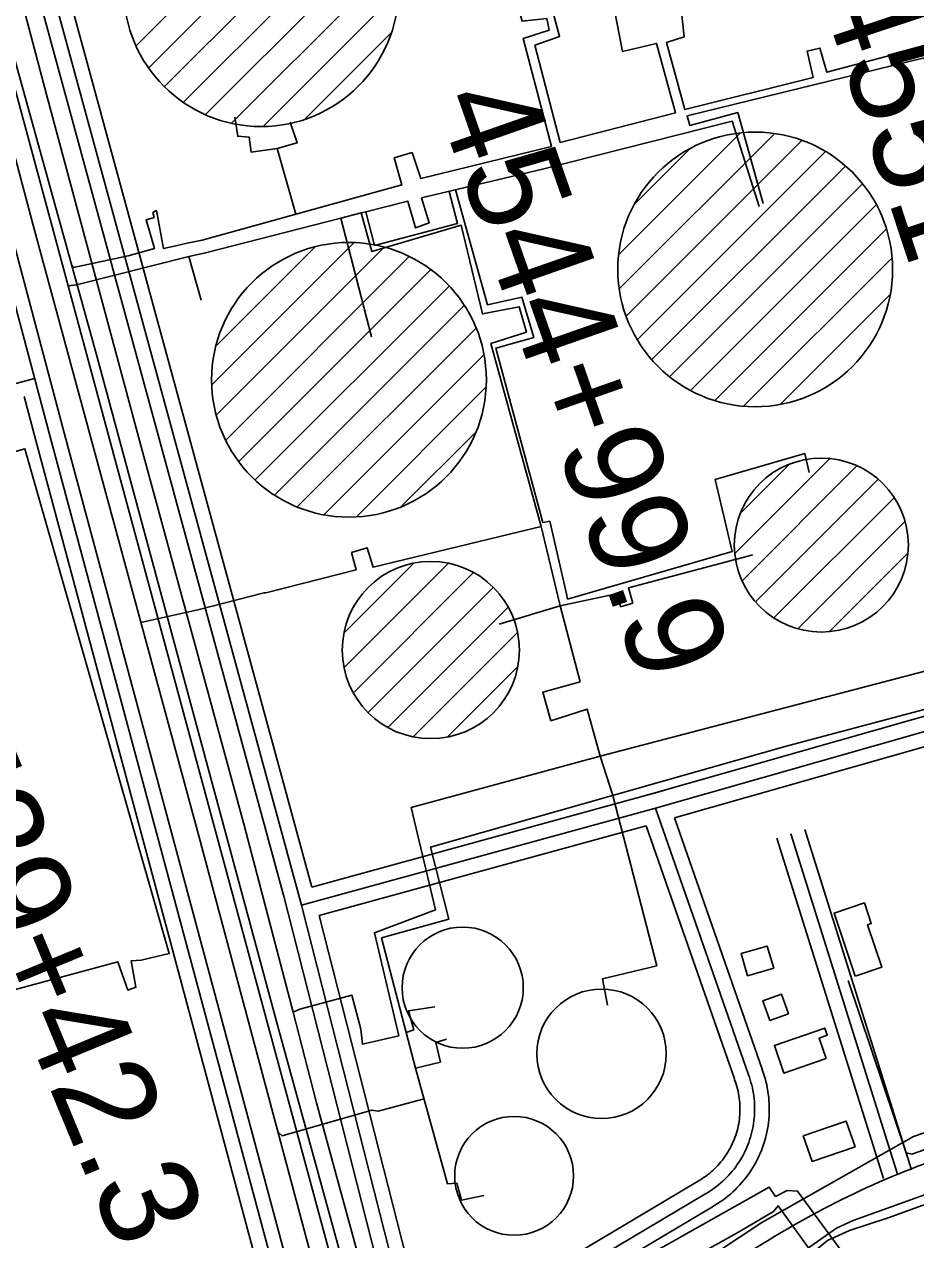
# Model space of a CAD drawing. Extents: x 3508733 to 3546731, y 546897 to 572481.
# Drawn here: x 3514220 to 3515132, y 565615 to 566859 of the extents above; entities that cross this region are included whole.
import ezdxf

# ---------------------------------------------------------------- set-up
doc = ezdxf.new("R2010")
doc.units = 0
for name, color, linetype in [('V-BLDG-OTLN', 7, 'Continuous'), ('V-DOMW-TANK', 7, 'Continuous'), ('V-LEVE-TOET', 7, 'Continuous'), ('V-ROAD-CNTR', 7, 'Continuous'), ('V-SITE-OTLN', 7, 'Continuous'), ('V-SURV-IDEN', 7, 'Continuous'), ('V-TOPO-SHOR', 7, 'Continuous'), ('V-UTIL-LINE', 7, 'Continuous')]:
    doc.layers.add(name, color=color, linetype=linetype)

msp = doc.modelspace()

# ---------------------------------------------------------------- linework, layer by layer
at = {"layer": 'V-BLDG-OTLN'}
for points in [[(3515069.8, 565884.8), (3515048.2, 565949.4), (3515079.3, 565959.8), (3515086.3, 565938.6), (3515082.6, 565937.4), (3515097.1, 565893.9)], [(3514986.5, 565892.9), (3514959.8, 565885.3), (3514953.4, 565907.9), (3514980, 565915.5)], [(3515001.7, 565846.3), (3514982.5, 565839.5), (3514975.4, 565859.6), (3514994.6, 565866.3)], [(3515040.1, 565800.5), (3514996.9, 565785.7), (3514987.3, 565813.9), (3515038.8, 565831.6), (3515041.3, 565824.3), (3515032.9, 565821.4)], [(3515069.7, 565710.3), (3515025.7, 565695.2), (3515016.7, 565721.3), (3515060.6, 565736.5)]]:
    msp.add_lwpolyline(points, close=True, dxfattribs=at)
at = {"layer": 'V-DOMW-TANK'}
for p, q in [((3514334.5, 566836.5), (3514520.3, 567022.3)), ((3514347.5, 566814.1), (3514542.8, 567009.5)), ((3514363.5, 566794.8), (3514562, 566993.3)), ((3514383, 566778.9), (3514578.1, 566974)), ((3514405.6, 566766.2), (3514590.7, 566951.3)), ((3514432.2, 566757.4), (3514599.4, 566924.7)), ((3514464.3, 566754.1), (3514602.7, 566892.6)), ((3514507, 566761.5), (3514595.6, 566850.1)), ((3514828.2, 566623.1), (3514952.3, 566747.2)), ((3514828.7, 566588.2), (3514987.2, 566746.7)), ((3514835.8, 566559.9), (3515015.4, 566739.6)), ((3514844.2, 566674.5), (3514900.9, 566731.1)), ((3514847, 566535.8), (3515039.5, 566728.3)), ((3514862, 566515.5), (3515059.9, 566713.4)), ((3514879.9, 566498), (3515077.3, 566695.4)), ((3514901.4, 566484.1), (3515091.3, 566674)), ((3514926.2, 566473.6), (3515101.8, 566649.2)), ((3514411.9, 566489.7), (3514557.6, 566635.3)), ((3514416.2, 566529.3), (3514517.8, 566630.9)), ((3514416.6, 566459), (3514588.2, 566630.6)), ((3514426.2, 566433.2), (3514613.9, 566620.9)), ((3514955.7, 566467.8), (3515107.4, 566619.4)), ((3514439.5, 566411.2), (3514636, 566607.7)), ((3514456.3, 566392.6), (3514654.5, 566590.8)), ((3514993, 566469.7), (3515105.6, 566582.3)), ((3514476, 566377), (3514670.2, 566571.2)), ((3514499.4, 566365), (3514682.2, 566547.7)), ((3514526.6, 566356.9), (3514690.2, 566520.4)), ((3514559.8, 566354.7), (3514692.3, 566487.2)), ((3514605.4, 566364.9), (3514681.9, 566441.4)), ((3514946.7, 566317.3), (3515043.6, 566414.2)), ((3514952.4, 566358.3), (3515002.4, 566408.4)), ((3514954.2, 566289.4), (3515071.6, 566406.8)), ((3514967.9, 566267.8), (3515093.2, 566393.1)), ((3514986.8, 566251.3), (3515109.6, 566374.2)), ((3515011.1, 566240.3), (3515120.6, 566349.8)), ((3515043.5, 566237.3), (3515123.8, 566317.7)), ((3514547.2, 566200.6), (3514653.6, 566307.1)), ((3514547.3, 566236.1), (3514618.3, 566307.1)), ((3514556.7, 566174.8), (3514679.6, 566297.7)), ((3514571.8, 566154.5), (3514699.7, 566282.4)), ((3514591.9, 566139.3), (3514714.9, 566262.3)), ((3514617.7, 566129.7), (3514724.4, 566236.5)), ((3514653.1, 566129.8), (3514724.5, 566201.2))]:
    msp.add_line(p, q, dxfattribs=at)
for centre, radius in [((3514462.4, 566894.5), 140.5), ((3514967.6, 566607.8), 140.5), ((3514552.2, 566494.9), 140.5), ((3515035.2, 566325.8), 89), ((3514635.9, 566218.4), 90.6), ((3514668.5, 565873), 62), ((3514810.5, 565805.4), 66.2), ((3514721.1, 565680.5), 60.8)]:
    msp.add_circle(centre, radius, dxfattribs=at)
at = {"layer": 'V-LEVE-TOET'}
msp.add_lwpolyline([(3514850.8, 565476.6), (3514903.4, 565510.7), (3515017.6, 565594.7), (3515041.7, 565614.3), (3515064, 565624.5), (3515103.4, 565637.7), (3515402.4, 565746.1), (3515714.9, 565848.8), (3515765.6, 565860.9), (3516060.6, 565934), (3516227.3, 565973.3), (3516431, 566026.4), (3516563, 566047.8)], dxfattribs=at)
at = {"layer": 'V-ROAD-CNTR'}
for points in [[(3514503.5, 565957.3), (3514208.7, 567040.6), (3514013, 567794.7)], [(3514547.8, 565330.7), (3514512.1, 565447.2), (3514246.5, 566436.7), (3513987, 567414.4), (3513945.8, 567576.4)], [(3514485.1, 565967.8), (3514197.9, 567023.2)], [(3514514.1, 565975.8), (3514226.9, 567030.9)], [(3514562.1, 565335), (3514526.5, 565451.4), (3514261, 566440.6), (3514112.4, 567000.6)], [(3513312, 566249), (3514230.7, 566496.3)], [(3514494.6, 565454.6), (3514232, 566432.8), (3514220, 566477.9)], [(3515710.1, 566312.9), (3514859.2, 566070.6), (3514514.1, 565975.8)], [(3515714.2, 566298.4), (3514863.3, 566056.1), (3514503.5, 565957.3), (3514615.1, 565518.5)], [(3515326.2, 566172.3), (3514885.1, 566046.8)], [(3514875.3, 566075), (3514859.5, 566070.6)], [(3514960.4, 565784.8), (3514865.8, 566056.8), (3514862.5, 566055.9)], [(3514856.2, 566038.6), (3514521.7, 565946.7), (3514629.7, 565522.2)], [(3514946.3, 565779.8), (3514856.2, 566038.6)], [(3514974.6, 565789.7), (3514885.1, 566046.8)], [(3515098.9, 565677.7), (3514989.6, 566025.9)], [(3515113.2, 565682.2), (3515003.9, 566030.4)], [(3515127.5, 565686.7), (3515018.2, 566034.9)], [(3514485.4, 565967.9), (3514485.4, 565967.9), (3514600.6, 565514.9)], [(3514923.8, 565648.8), (3514926.4, 565650.4), (3514929.2, 565652.1), (3514931.9, 565653.9), (3514934.6, 565655.8), (3514937.2, 565657.7), (3514939.7, 565659.7), (3514942.2, 565661.8), (3514944.6, 565664), (3514947, 565666.2), (3514949.3, 565668.5), (3514951.5, 565670.9), (3514953.7, 565673.3), (3514955.8, 565675.8), (3514957.9, 565678.4), (3514959.8, 565681), (3514961.7, 565683.6), (3514963.5, 565686.3), (3514965.2, 565689.1), (3514966.9, 565691.9), (3514968.5, 565694.7), (3514970, 565697.6), (3514971.4, 565700.6), (3514972.7, 565703.5), (3514973.9, 565706.5), (3514975.1, 565709.6), (3514976.2, 565712.7), (3514977.1, 565715.8), (3514978, 565718.9), (3514978.8, 565722), (3514979.6, 565725.2), (3514980.2, 565728.4), (3514980.7, 565731.6), (3514981.2, 565734.8), (3514981.5, 565738.1), (3514981.8, 565741.3), (3514982, 565744.6), (3514982, 565747.8), (3514982, 565751.1), (3514981.9, 565754.3), (3514981.7, 565757.6), (3514981.4, 565760.8), (3514981, 565764.1), (3514980.6, 565767.3), (3514980, 565770.5), (3514979.4, 565773.7), (3514978.6, 565776.9), (3514977.8, 565780), (3514976.9, 565783.1), (3514975.9, 565786.2), (3514974.8, 565789.2), (3514974.5, 565790.1)], [(3514908.6, 565674.7), (3514910.9, 565676), (3514912.9, 565677.3), (3514914.9, 565678.7), (3514916.9, 565680), (3514918.8, 565681.5), (3514920.7, 565683), (3514922.6, 565684.5), (3514924.4, 565686.1), (3514926.1, 565687.8), (3514927.8, 565689.5), (3514929.5, 565691.2), (3514931.1, 565693), (3514932.6, 565694.9), (3514934.1, 565696.7), (3514935.6, 565698.7), (3514937, 565700.6), (3514938.3, 565702.6), (3514939.6, 565704.7), (3514940.8, 565706.7), (3514942, 565708.9), (3514943.1, 565711), (3514944.1, 565713.2), (3514945.1, 565715.4), (3514946, 565717.6), (3514946.9, 565719.8), (3514947.7, 565722.1), (3514948.4, 565724.4), (3514949.1, 565726.7), (3514949.7, 565729.1), (3514950.2, 565731.4), (3514950.7, 565733.8), (3514951.1, 565736.1), (3514951.4, 565738.5), (3514951.7, 565740.9), (3514951.8, 565743.3), (3514952, 565745.7), (3514952, 565748.1), (3514952, 565750.5), (3514951.9, 565752.9), (3514951.8, 565755.3), (3514951.6, 565757.7), (3514951.3, 565760.1), (3514951, 565762.5), (3514950.5, 565764.9), (3514950.1, 565767.3), (3514949.5, 565769.6), (3514948.9, 565771.9), (3514948.2, 565774.2), (3514947.5, 565776.5), (3514946.6, 565778.9), (3514946.4, 565779.5)], [(3514916.2, 565661.8), (3514918.7, 565663.2), (3514921.1, 565664.7), (3514923.4, 565666.3), (3514925.7, 565667.9), (3514928, 565669.6), (3514930.2, 565671.4), (3514932.4, 565673.2), (3514934.5, 565675.1), (3514936.6, 565677), (3514938.6, 565679), (3514940.5, 565681.1), (3514942.4, 565683.2), (3514944.2, 565685.3), (3514946, 565687.5), (3514947.7, 565689.8), (3514949.3, 565692.1), (3514950.9, 565694.5), (3514952.4, 565696.9), (3514953.9, 565699.3), (3514955.2, 565701.8), (3514956.5, 565704.3), (3514957.8, 565706.9), (3514958.9, 565709.4), (3514960, 565712.1), (3514961, 565714.7), (3514961.9, 565717.4), (3514962.8, 565720.1), (3514963.6, 565722.8), (3514964.3, 565725.5), (3514964.9, 565728.3), (3514965.4, 565731.1), (3514965.9, 565733.9), (3514966.3, 565736.7), (3514966.6, 565739.5), (3514966.8, 565742.3), (3514967, 565745.2), (3514967, 565748), (3514967, 565750.8), (3514966.9, 565753.6), (3514966.8, 565756.5), (3514966.5, 565759.3), (3514966.2, 565762.1), (3514965.8, 565764.9), (3514965.3, 565767.7), (3514964.7, 565770.5), (3514964.1, 565773.2), (3514963.3, 565776), (3514962.5, 565778.7), (3514961.7, 565781.4), (3514960.7, 565784), (3514960.4, 565784.8)], [(3514645.5, 565518), (3514908.5, 565674.7)], [(3514653.2, 565505.1), (3514916.2, 565661.8)], [(3514660.9, 565492.2), (3514923.9, 565648.9)]]:
    msp.add_lwpolyline(points, dxfattribs=at)
msp.add_arc((3515450.5, 564860), 888.6, 106.2989, 120.8986, dxfattribs=at)
msp.add_spline([(3514994.1, 565622.5), (3514938.8, 565588.4), (3514863.1, 565536.1), (3514798.9, 565488.5)], degree=3, dxfattribs=at)
at = {"layer": 'V-SITE-OTLN'}
for p, q in [((3515332.7, 565790.4), (3515129.4, 565720.9)), ((3515129.4, 565720.9), (3514974.5, 565632.9)), ((3514974.5, 565632.9), (3514744.7, 565480.9))]:
    msp.add_line(p, q, dxfattribs=at)
at = {"layer": 'V-TOPO-SHOR'}
for points in [[(3514863.5, 565495.7), (3515050.9, 565627.1), (3515067.9, 565634.9), (3515279.2, 565711), (3515615.8, 565829.1), (3515828.4, 565889.9), (3516048, 565941.3), (3516248.3, 565989.7), (3516390.8, 566027.7), (3516503.2, 566052.5), (3516549.8, 566062.8)], [(3515062.5, 565880.4), (3515121.9, 565704), (3515127.8, 565702.8), (3515388.3, 565793.9), (3515600, 565864.1), (3515826.4, 565933.7), (3515868.2, 565949.9), (3515870.5, 565952.3), (3515871.1, 565956.4), (3515871, 565963.5)]]:
    msp.add_lwpolyline(points, dxfattribs=at)
at = {"layer": 'V-UTIL-LINE'}
for p, q in [((3514543.9, 566660.2), (3514575.3, 566538.9)), ((3514388.5, 566621.1), (3514401.2, 566576.3)), ((3514610.8, 565827.3), (3514620.4, 565790.8))]:
    msp.add_line(p, q, dxfattribs=at)
for points in [[(3514012.1, 567525.4), (3514056.7, 567361.1), (3514174.2, 566927.7), (3514312.9, 566414.2), (3514566.7, 565474.4), (3514577.5, 565440.8), (3514585.7, 565446.2), (3514601.1, 565454.3)], [(3514585.7, 565446.2), (3514479, 565834.8), (3514294.6, 566517.9), (3514197, 566871.8), (3514024.9, 567528.9)], [(3515570.3, 565120.2), (3515154.8, 565462.2), (3515060.9, 565596.7), (3515010.9, 565664.9), (3515000.3, 565665.4), (3514988.5, 565659.4), (3514982, 565668.8), (3514601.1, 565454.3), (3514519.1, 565755.2), (3514495, 565847.9), (3514445.5, 566037.8), (3514339.4, 566427.7), (3514243, 566786.9), (3514133.8, 567198.5), (3514046.6, 567521.1)], [(3513278.9, 567248.9), (3513718.2, 567368.9), (3513928.4, 567426.1), (3513935.5, 567427.9), (3514019.1, 567446.7), (3514018.5, 567446.1), (3514027.6, 567403.7), (3514125.3, 567041.6), (3514126.6, 567029.2), (3514138, 566990.9), (3514140.4, 566988), (3514229.6, 566651.7), (3514399, 566027), (3514556.3, 565438.7)], [(3515177.8, 567412.5), (3515185.1, 567375.3), (3515166.8, 567367.6), (3515171.1, 567346.4), (3514903.1, 567274), (3514896.5, 567297), (3514887.7, 567294.6), (3514892.6, 567269.2), (3514644.1, 567201.7), (3514693.4, 567028), (3514733.3, 566868.4), (3514759.2, 566876.9), (3514767.6, 566846.2), (3514742.3, 566837.2), (3514768.3, 566737.7), (3514886, 566767.9), (3514866.8, 566839.1), (3514832, 566830.7), (3514824.1, 566871.3)], [(3514375, 566632.1), (3514386.7, 566634.6), (3514402, 566637.7), (3514606.3, 566694.3), (3514598.5, 566722), (3514616.7, 566727.4), (3514625.7, 566700.9), (3514759.4, 566733.5), (3514730.5, 566844.2), (3514757, 566852.7), (3514754.5, 566864.4), (3514729.2, 566861.9), (3514665.4, 567089.8), (3514633.4, 567208.8), (3514760.6, 567246.1), (3514754, 567269), (3514726.9, 567263), (3514716.1, 567294.8)], [(3514891.3, 566880.6), (3514895, 566845.8), (3514876.8, 566839.8), (3514895.5, 566771.5), (3515026.8, 566804.1), (3515020.7, 566831.2), (3515033.7, 566834.2), (3515040.9, 566809.5), (3515291.2, 566875.8), (3515270.7, 566953), (3515237.7, 566944.5), (3515231, 566976.9)], [(3515140.5, 566824.2), (3515260.4, 566386.1), (3515244.6, 566376.6), (3515285.5, 566234.7), (3514809.1, 566109.8), (3514615.9, 566057.4), (3514640.7, 565952.6), (3514578.3, 565929.2), (3514603.1, 565823.8), (3514566, 565815.3), (3514564.2, 565830.6), (3514555.1, 565865.4), (3514502.1, 565850.9), (3514495, 565847.9)], [(3515140.5, 566824.2), (3514897.9, 566765), (3514900.9, 566755), (3514949.7, 566768.3), (3514975.6, 566675.2)], [(3514971.5, 566672.3), (3514943.9, 566759.4), (3514750.1, 566710.5), (3514626.5, 566680.9), (3514634.3, 566655.5), (3514620.1, 566650.2), (3514612.3, 566677.8), (3514569.5, 566666.8), (3514564.6, 566665.6), (3514543.9, 566660.2), (3514405.6, 566624.7), (3514388.5, 566621.1), (3514273.7, 566592.1), (3514265.1, 566591.2)], [(3514478.7, 566731.4), (3514452.2, 566727.7), (3514450.3, 566743), (3514438.5, 566744.1), (3514435.5, 566763.6)], [(3514498, 566664.3), (3514478.7, 566731.4), (3514499.3, 566737.4), (3514492.1, 566758.6)], [(3514654.7, 566687.6), (3514663.2, 566654.7), (3514578.4, 566632.3), (3514569.5, 566666.8)], [(3514774.5, 566276), (3514757.5, 566350.2), (3514750.5, 566348.9), (3514702.3, 566527.4), (3514741.1, 566538.2), (3514729.1, 566579.4), (3514693.7, 566571.6), (3514661.1, 566689.2)], [(3514375, 566632.1), (3514362.7, 566629.1), (3514355.4, 566668), (3514351.8, 566666.2), (3514353.1, 566660.9), (3514344.8, 566658.5), (3514353.2, 566629.1), (3514326.3, 566621.7)], [(3514564.6, 566665.6), (3514575.7, 566626.2), (3514667, 566653), (3514688.7, 566562.3), (3514726.4, 566569.6), (3514733.7, 566543.7), (3514697.2, 566532.2), (3514748.7, 566344.8)], [(3514268.3, 566613.3), (3514270.6, 566609.8), (3514326.3, 566621.7)], [(3513987.4, 565810.7), (3514316, 565899.4), (3514326.2, 565870.5), (3514334.4, 565873.5), (3514329.5, 565900.6), (3514339.6, 565901.3), (3514368.4, 565907.9), (3514220.9, 566424.3), (3514104.7, 566392)], [(3514774.5, 566276), (3514775.7, 566270.6), (3514944.1, 566319.4), (3514926.6, 566393), (3515018.4, 566419.5), (3515022.7, 566400.1)], [(3515282.2, 566394.5), (3515323.3, 566229), (3515328.7, 566207.8), (3515000.7, 566120.4), (3514635.6, 566016.8), (3514654.3, 565943.2), (3514585.5, 565923.9), (3514610.8, 565827.3), (3514618.4, 565829.8), (3514613, 565849.2), (3514640.1, 565853.5)], [(3514768.1, 566263.5), (3514748.7, 566344.8), (3514576.8, 566303.1), (3514570.7, 566323.1), (3514554.8, 566318.3), (3514559.7, 566300.6), (3514467.2, 566277.1), (3514465.4, 566277.1), (3514397.7, 566259.6), (3514339.5, 566246.5)], [(3514768.1, 566263.5), (3514827, 566276.3), (3514830, 566262.7), (3514842.4, 566266.3), (3514838.1, 566282.2), (3514965.3, 566316)], [(3514821.9, 566069.7), (3514809.1, 566109.8), (3514795.8, 566158.1), (3514758.7, 566146.1), (3514750.3, 566175.5), (3514788.6, 566185.8), (3514768.1, 566263.5), (3514705.7, 566244.9)], [(3514816.5, 565855.1), (3514811.6, 565882.2), (3514866.9, 565895.5), (3514821.9, 566069.7)], [(3514652.1, 565820.5), (3514640.9, 565816.9), (3514645.8, 565796.9), (3514620.4, 565790.8), (3514653, 565672.5), (3514662.4, 565673.1), (3514667.2, 565655.5), (3514690.2, 565660.3)], [(3514479.6, 565725.4), (3514483.8, 565721.3), (3514575.6, 565747.8), (3514582.1, 565746.6), (3514629.1, 565759.3)], [(3514517.1, 564568.1), (3514289.5, 565081.5), (3514267.4, 565130.9), (3514262.6, 565141.5), (3514226.8, 565212.6), (3514226.2, 565220.3), (3514240.3, 565221), (3514497.2, 565367), (3514506, 565378.2), (3514563, 565408), (3514574.8, 565412.2), (3514644.7, 565452.8), (3514652.4, 565455.8), (3514952.2, 565623.8), (3514986.3, 565644.1), (3514991, 565650), (3515061.1, 565553.1), (3515134.2, 565453.8), (3515394.4, 565240.1), (3515559.8, 565105.4)]]:
    msp.add_lwpolyline(points, dxfattribs=at)

# ---------------------------------------------------------------- texts
at = {"layer": 'V-SURV-IDEN'}
for s, rotation, p in [('4551+07.3', 288.2881, (3515033.1, 566891.4)), ('4544+99.9', 289.3098, (3514640.4, 566781)), ('4539+42.3', 292.4698, (3514072.8, 566189))]:
    msp.add_text(s, height=100, rotation=rotation, dxfattribs=at).set_placement(p)

doc.saveas('drawing.dxf')
